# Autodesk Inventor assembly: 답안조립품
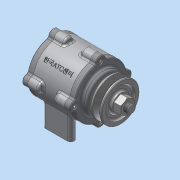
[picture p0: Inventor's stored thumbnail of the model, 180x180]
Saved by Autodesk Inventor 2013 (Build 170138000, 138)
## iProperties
Created: 2015-03
Part Number: 답안조립품
Document SubType Name: Assembly
Designer: 교육생
Author: 교육생
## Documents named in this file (11)
- C:\Documents and Settings\교육생\바탕 화면\450305V1024\답안조립품.iam
- C:\Documents and Settings\교육생\바탕 화면\450305V1024\본체.ipt
- C:\Documents and Settings\교육생\바탕 화면\450305V1024\커버.ipt
- C:\Documents and Settings\교육생\바탕 화면\450305V1024\커버2.ipt
- C:\Documents and Settings\교육생\바탕 화면\450305V1024\베어링 6204.ipt
- C:\Documents and Settings\교육생\바탕 화면\450305V1024\축.ipt
- C:\Documents and Settings\교육생\바탕 화면\450305V1024\키(4 x 4 x 12).ipt
- C:\Documents and Settings\교육생\바탕 화면\450305V1024\V벨트풀리.ipt
- C:\Documents and Settings\교육생\바탕 화면\450305V1024\너트 M12x1.25.ipt
- C:\Documents and Settings\교육생\바탕 화면\450305V1024\오일실.ipt
- C:\Documents and Settings\교육생\바탕 화면\450305V1024\M 4 x 12.ipt
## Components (14 placed, 6 different names)
1. KS B 2023 6204 - 20 x 47 x 14:1
2. KS B 2023 6204 - 20 x 47 x 14:2
3. KS B 1311 (I) 4 x 4 x 12:1
4. 그루브 풀리1:1
5. KS B 1012 클래스 1 일반 - 미터 M12x1.25:1
6. KS B 2804 D D - 20 32 8:1
7. KS B 1003 - 미터 M 4 x 12:1
8. KS B 1003 - 미터 M 4 x 12:3
9. KS B 1003 - 미터 M 4 x 12:4
10. KS B 1003 - 미터 M 4 x 12:5
11. KS B 1003 - 미터 M 4 x 12:2
12. KS B 1003 - 미터 M 4 x 12:6
13. KS B 1003 - 미터 M 4 x 12:7
14. KS B 1003 - 미터 M 4 x 12:8
